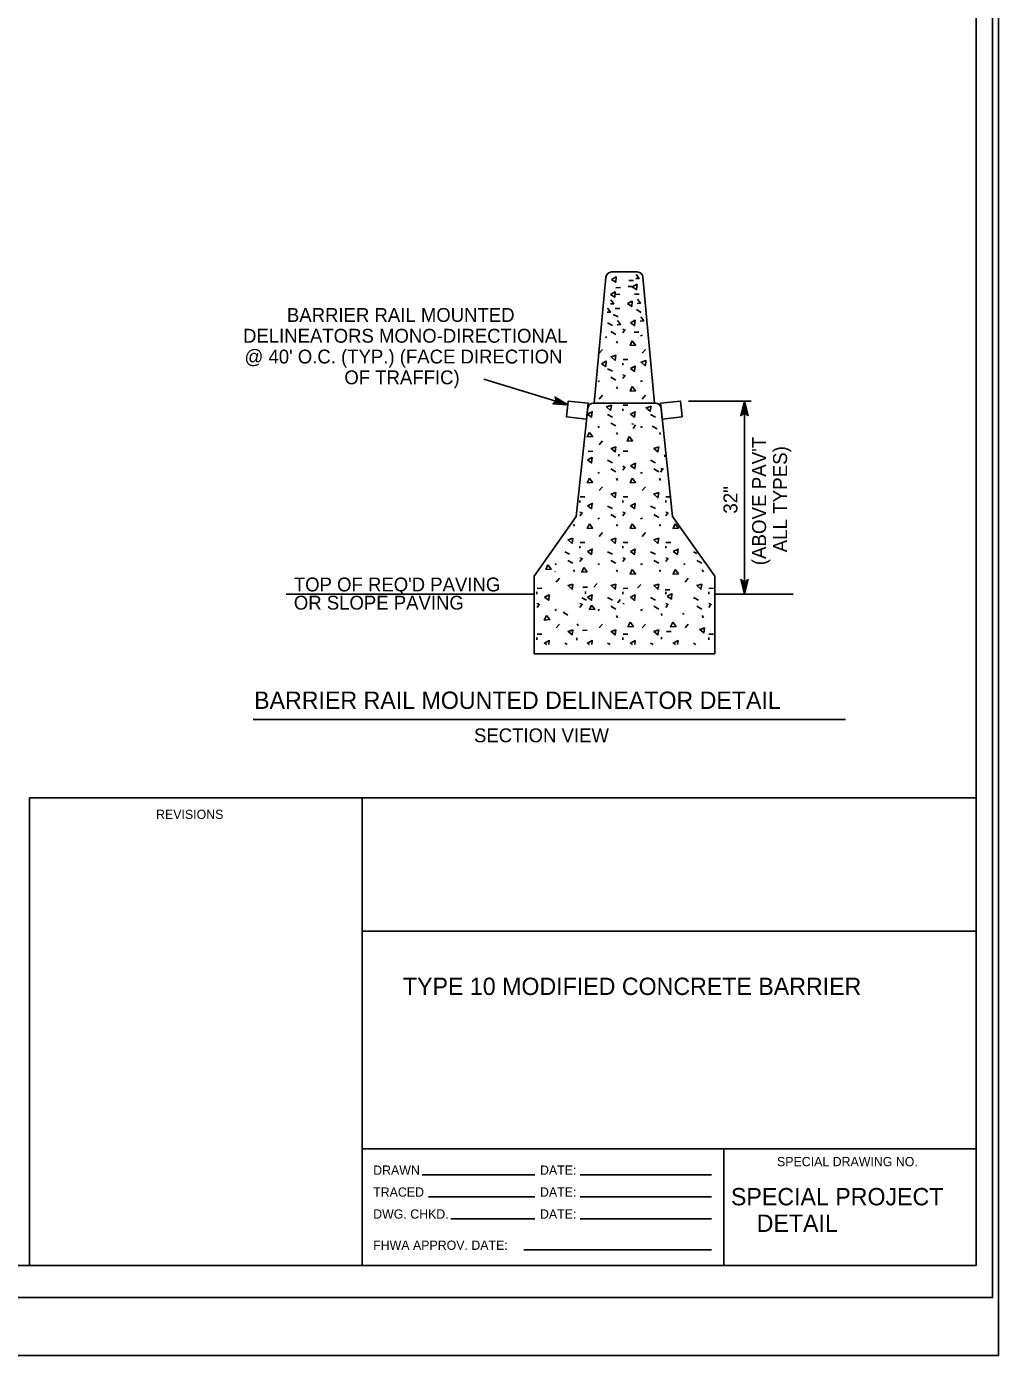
# Model space of a CAD drawing. Extents: x 504255 to 505955, y 659986 to 661086.
# Drawn here: x 505553 to 505955, y 659986 to 660536 of the extents above; entities that cross this region are included whole.
import ezdxf

# ---------------------------------------------------------------- set-up
doc = ezdxf.new("R2010")
doc.units = 0
for name, color, linetype in [('Level 62', 7, 'Continuous'), ('Level1', 7, 'Continuous'), ('Level3', 7, 'Continuous'), ('Level63', 7, 'Continuous')]:
    doc.layers.add(name, color=color, linetype=linetype)

msp = doc.modelspace()

# ---------------------------------------------------------------- linework, layer by layer
at = {"layer": 'Level 62'}
msp.add_lwpolyline([(505955.48, 661086.39), (504255.48, 661086.39), (504255.48, 659986.39), (505955.48, 659986.39)], close=True, dxfattribs=at)
at = {"layer": 'Level1'}
for p, q in [((505792.97, 660432.68), (505788.18, 660380.52)), ((505808.33, 660432.68), (505813.12, 660380.52)), ((505742.45, 660390.42), (505777.23, 660379.88)), ((505853.11, 660381.38), (505827.17, 660381.38)), ((505850.32, 660301.52), (505850.32, 660381.38)), ((505823.29, 660328.72), (505823.29, 660328.72)), ((505838.06, 660307.81), (505838.06, 660307.81)), ((505647.02, 660249.61), (505892.16, 660249.61)), ((505946.29, 660217.21), (505554.37, 660217.21)), ((505554.37, 660217.21), (505554.37, 660023.67)), ((505692.05, 660217.21), (505692.05, 660023.67)), ((505692.05, 660161.99), (505946.29, 660161.99)), ((505692.05, 660071.92), (505946.29, 660071.92)), ((505841.81, 660071.92), (505841.81, 660023.67)), ((505716.88, 660061.14), (505763.62, 660061.14)), ((505782.31, 660061.14), (505836.74, 660061.14)), ((505719.48, 660052.06), (505763.62, 660052.06)), ((505782.31, 660052.06), (505836.74, 660052.06)), ((505728.82, 660042.97), (505763.62, 660042.97)), ((505782.31, 660042.97), (505836.74, 660042.97)), ((505758.94, 660030.06), (505836.74, 660030.06)), ((505946.29, 660023.67), (505554.37, 660023.67))]:
    msp.add_line(p, q, dxfattribs=at)
for points in [[(504257.9, 660010.3), (505953.07, 660010.3), (505953.07, 661062.47), (504257.9, 661062.47), (504257.9, 660010.3)], [(504327.92, 660023.67), (505946.29, 660023.67), (505946.29, 661038.56), (504327.92, 661038.56), (504327.92, 660023.67)], [(505795.35, 660434.83), (505805.95, 660434.83)], [(505771.02, 660380.2), (505777.23, 660379.88), (505771.91, 660383.05), (505772.44, 660382.37), (505773.43, 660382.07), (505772.32, 660381.89), (505775.22, 660381.01), (505772.5, 660381.31), (505774.92, 660380.06), (505772.03, 660380.93), (505772.85, 660380.16), (505771.86, 660380.47), (505771.02, 660380.2), (505772.43, 660381.34), (505771.91, 660383.05)], [(505787.84, 660380.52), (505813.46, 660380.52)], [(505848.81, 660375.4), (505850.32, 660381.38), (505851.83, 660375.4), (505851.33, 660376.11), (505851.33, 660377.14), (505850.82, 660376.15), (505850.82, 660379.13), (505850.32, 660376.48), (505849.82, 660379.13), (505849.82, 660376.15), (505849.31, 660377.14), (505849.31, 660376.11), (505848.81, 660375.4), (505850.32, 660376.4), (505851.83, 660375.4)], [(505785.46, 660378.4), (505780.7, 660333.61)], [(505815.84, 660378.4), (505820.6, 660333.61)], [(505780.7, 660333.61), (505763.25, 660308.92)], [(505820.6, 660333.61), (505838.06, 660308.92)], [(505763.25, 660308.92), (505763.25, 660276.83)], [(505838.06, 660308.92), (505838.06, 660276.83)], [(505848.81, 660307.5), (505850.32, 660301.52), (505851.83, 660307.5), (505851.33, 660306.79), (505851.33, 660305.76), (505850.82, 660306.76), (505850.82, 660303.77), (505850.32, 660306.43), (505849.82, 660303.77), (505849.82, 660306.76), (505849.31, 660305.76), (505849.31, 660306.79), (505848.81, 660307.5), (505850.32, 660306.5), (505851.83, 660307.5)], [(505838.06, 660276.83), (505763.25, 660276.83)]]:
    msp.add_lwpolyline(points, dxfattribs=at)
for points in [[(505776.7, 660374.82), (505784.99, 660373.96), (505785.68, 660380.52), (505777.39, 660381.38)], [(505824.61, 660374.82), (505816.32, 660373.96), (505815.62, 660380.52), (505823.91, 660381.38)], [(505771.89, 660310.84), (505771.89, 660310.83), (505771.9, 660310.84)]]:
    msp.add_lwpolyline(points, close=True, dxfattribs=at)
for centre, start_param, end_param in [((505795.35, 660432.46), 4.712389, 6.192092), ((505805.95, 660432.46), 3.232686, 4.712389), ((505787.84, 660378.15), 4.712389, 6.178514), ((505813.46, 660378.15), 3.24706, 4.712389)]:
    msp.add_ellipse(centre, major_axis=(-2.39, 0), ratio=0.99, start_param=start_param, end_param=end_param, dxfattribs=at)
at = {"layer": 'Level3'}
for p, q in [((505804.37, 660431.35), (505802.41, 660431.32)), ((505798.81, 660425.58), (505796.85, 660425.55)), ((505799.08, 660428.33), (505797.12, 660428.3)), ((505804.1, 660428.78), (505802.14, 660428.74)), ((505806.79, 660425.67), (505804.83, 660425.64)), ((505798.81, 660419.73), (505796.85, 660419.69)), ((505805.62, 660419.24), (505807.58, 660418.09)), ((505793.7, 660413.71), (505795.7, 660412.65)), ((505796.04, 660417.26), (505798.03, 660416.21)), ((505792.64, 660407.68), (505793.34, 660408.01)), ((505795.02, 660410.17), (505797.08, 660408.96)), ((505800.57, 660411.03), (505799.98, 660411.21)), ((505801.02, 660411.03), (505800.02, 660409.64)), ((505806.61, 660409.87), (505804.65, 660409.84)), ((505807.36, 660408.39), (505808.07, 660408.72)), ((505791.55, 660402.75), (505790.17, 660401.15)), ((505797.35, 660406.23), (505797.77, 660405.37)), ((505809.32, 660402.75), (505807.95, 660401.15)), ((505799.98, 660397.11), (505799.98, 660396.22)), ((505802.04, 660398.6), (505800.08, 660398.56)), ((505793.7, 660394.77), (505795.7, 660393.71)), ((505795.02, 660391.23), (505797.08, 660390.02)), ((505800.57, 660392.1), (505799.98, 660392.26)), ((505801.02, 660392.1), (505800.02, 660390.7)), ((505789.59, 660389.45), (505790.3, 660389.78)), ((505797.35, 660387.29), (505797.77, 660386.43)), ((505807.36, 660389.45), (505808.07, 660389.78)), ((505791.55, 660383.81), (505790.17, 660382.21)), ((505802.04, 660379.66), (505800.08, 660379.63)), ((505809.32, 660383.81), (505807.95, 660382.21)), ((505793.7, 660375.83), (505795.7, 660374.77)), ((505799.98, 660378.17), (505799.98, 660377.28)), ((505811.49, 660375.83), (505813.47, 660374.77)), ((505789.59, 660370.51), (505790.3, 660370.83)), ((505795.02, 660372.29), (505797.08, 660371.09)), ((505804.35, 660371.81), (505803.76, 660371.99)), ((505805.3, 660371.49), (505804.3, 660370.1)), ((505807.36, 660370.51), (505808.07, 660370.83)), ((505812.1, 660371.03), (505814.16, 660369.83)), ((505791.55, 660364.87), (505790.17, 660363.27)), ((505797.35, 660368.35), (505797.77, 660367.49)), ((505815.12, 660368.35), (505815.54, 660367.49)), ((505787.64, 660360.6), (505785.67, 660360.56)), ((505798.36, 660359.46), (505798.36, 660358.58)), ((505802.04, 660360.72), (505800.08, 660360.68)), ((505817.31, 660359.19), (505817.31, 660358.3)), ((505793.7, 660356.89), (505795.7, 660355.83)), ((505795.02, 660353.34), (505797.08, 660352.14)), ((505800.57, 660354.22), (505799.98, 660354.39)), ((505801.02, 660354.22), (505800.02, 660352.83)), ((505811.49, 660356.89), (505813.47, 660355.83)), ((505812.8, 660353.34), (505814.86, 660352.14)), ((505816.64, 660353.42), (505815.65, 660352.03)), ((505816.38, 660353.33), (505815.79, 660353.5)), ((505789.59, 660351.57), (505790.3, 660351.89)), ((505797.35, 660349.41), (505797.77, 660348.55)), ((505807.36, 660351.57), (505808.07, 660351.89)), ((505815.12, 660349.41), (505815.54, 660348.55)), ((505784.27, 660341.78), (505782.31, 660341.74)), ((505791.55, 660345.93), (505790.17, 660344.33)), ((505802.04, 660341.78), (505800.08, 660341.74)), ((505809.32, 660345.93), (505807.95, 660344.33)), ((505819.82, 660341.78), (505817.86, 660341.74)), ((505782.21, 660340.29), (505782.21, 660339.4)), ((505793.7, 660337.95), (505795.7, 660336.89)), ((505799.98, 660340.29), (505799.98, 660339.4)), ((505811.49, 660337.95), (505813.47, 660336.89)), ((505817.76, 660340.29), (505817.76, 660339.4)), ((505779.57, 660330.47), (505779.99, 660329.61)), ((505782.8, 660335.27), (505782.21, 660335.45)), ((505783.24, 660335.27), (505782.25, 660333.88)), ((505789.59, 660332.63), (505790.3, 660332.95)), ((505795.02, 660334.4), (505797.08, 660333.2)), ((505797.35, 660330.47), (505797.77, 660329.61)), ((505800.57, 660335.27), (505799.98, 660335.45)), ((505801.02, 660335.27), (505800.02, 660333.88)), ((505807.36, 660332.63), (505808.07, 660332.95)), ((505812.8, 660334.4), (505814.86, 660333.2)), ((505815.12, 660330.47), (505815.54, 660329.61)), ((505818.35, 660335.27), (505817.76, 660335.45)), ((505818.79, 660335.27), (505817.8, 660333.88)), ((505791.55, 660326.99), (505790.17, 660325.39)), ((505809.32, 660326.99), (505807.95, 660325.39)), ((505775.93, 660319.01), (505777.92, 660317.96)), ((505782.21, 660321.35), (505782.21, 660320.47)), ((505784.27, 660322.84), (505782.31, 660322.8)), ((505793.7, 660319.01), (505795.7, 660317.96)), ((505799.98, 660321.35), (505799.98, 660320.47)), ((505802.04, 660322.84), (505800.08, 660322.8)), ((505811.49, 660319.01), (505813.47, 660317.96)), ((505817.76, 660321.35), (505817.76, 660320.47)), ((505819.82, 660322.84), (505817.86, 660322.8)), ((505829.26, 660319.01), (505830.68, 660318.25)), ((505771.81, 660313.7), (505772.51, 660314.01)), ((505777.25, 660315.46), (505779.31, 660314.26)), ((505782.8, 660316.34), (505782.21, 660316.51)), ((505783.24, 660316.34), (505782.25, 660314.94)), ((505789.59, 660313.7), (505790.3, 660314.01)), ((505795.02, 660315.46), (505797.08, 660314.26)), ((505800.57, 660316.34), (505799.98, 660316.51)), ((505801.02, 660316.34), (505800.02, 660314.94)), ((505807.36, 660313.7), (505808.07, 660314.01)), ((505812.8, 660315.46), (505814.86, 660314.26)), ((505818.35, 660316.34), (505817.76, 660316.51)), ((505818.79, 660316.34), (505817.8, 660314.94)), ((505825.14, 660313.7), (505825.84, 660314.01)), ((505830.58, 660315.46), (505832.63, 660314.26)), ((505773.77, 660308.05), (505772.4, 660306.45)), ((505779.57, 660311.53), (505779.99, 660310.67)), ((505797.35, 660311.53), (505797.77, 660310.67)), ((505815.12, 660311.53), (505815.54, 660310.67)), ((505827.09, 660308.05), (505825.73, 660306.45)), ((505832.9, 660311.53), (505833.32, 660310.67)), ((505766.49, 660303.9), (505764.53, 660303.86)), ((505785.33, 660304.34), (505783.37, 660304.3)), ((505784.58, 660302.54), (505784.58, 660301.65)), ((505789.32, 660305.94), (505787.95, 660304.34)), ((505802.04, 660303.9), (505800.08, 660303.86)), ((505807.46, 660305.5), (505806.08, 660303.9)), ((505819.46, 660303.26), (505817.49, 660303.22)), ((505837.59, 660303.9), (505835.63, 660303.86)), ((505764.43, 660302.41), (505764.43, 660301.52)), ((505765.02, 660297.4), (505764.43, 660297.57)), ((505765.47, 660297.4), (505764.48, 660296)), ((505782.8, 660297.4), (505782.21, 660297.57)), ((505783.24, 660297.4), (505782.25, 660296)), ((505783, 660300.01), (505784.99, 660298.95)), ((505793.7, 660300.07), (505795.7, 660299.02)), ((505798.85, 660299.32), (505797.86, 660297.93)), ((505799.98, 660302.41), (505799.98, 660301.52)), ((505800.57, 660297.4), (505799.98, 660297.57)), ((505811.49, 660300.07), (505813.47, 660299.02)), ((505817.76, 660302.41), (505817.76, 660301.52)), ((505818.35, 660297.4), (505817.76, 660297.57)), ((505818.79, 660297.4), (505817.8, 660296)), ((505829.26, 660300.07), (505831.25, 660299.02)), ((505835.53, 660302.41), (505835.53, 660301.52)), ((505836.13, 660297.4), (505835.53, 660297.57)), ((505836.57, 660297.4), (505835.58, 660296)), ((505771.81, 660294.75), (505772.51, 660295.08)), ((505775.23, 660294.02), (505777.29, 660292.81)), ((505789.59, 660294.75), (505790.3, 660295.08)), ((505795.02, 660296.53), (505797.08, 660295.32)), ((505797.35, 660292.59), (505797.77, 660291.73)), ((505807.36, 660294.75), (505808.07, 660295.08)), ((505812.8, 660296.53), (505814.86, 660295.32)), ((505815.81, 660293.5), (505816.23, 660292.63)), ((505824.68, 660293.16), (505825.39, 660293.49)), ((505830.58, 660296.53), (505832.63, 660295.32)), ((505832.9, 660292.59), (505833.32, 660291.73)), ((505773.77, 660289.11), (505772.4, 660287.52)), ((505781.06, 660289.2), (505781.48, 660288.33)), ((505785.27, 660286.52), (505783.31, 660286.47)), ((505791.55, 660289.11), (505790.17, 660287.52)), ((505809.32, 660289.11), (505807.95, 660287.52)), ((505820.03, 660286.06), (505818.07, 660286.02)), ((505827.09, 660289.11), (505825.73, 660287.52)), ((505764.43, 660283.47), (505764.43, 660282.58)), ((505766.49, 660284.96), (505764.53, 660284.92)), ((505775.93, 660281.13), (505776.92, 660280.61)), ((505780.96, 660283.34), (505780.96, 660282.45)), ((505793.7, 660281.13), (505794.7, 660280.61)), ((505799.98, 660283.47), (505799.98, 660282.58)), ((505802.04, 660284.96), (505800.08, 660284.92)), ((505811.49, 660281.13), (505812.48, 660280.61)), ((505815.96, 660283.67), (505815.96, 660282.79)), ((505829.26, 660281.13), (505830.25, 660280.61)), ((505835.53, 660283.47), (505835.53, 660282.58)), ((505837.59, 660284.96), (505835.63, 660284.92))]:
    msp.add_line(p, q, dxfattribs=at)
for points in [[(505795.32, 660431.74), (505797.06, 660430.55), (505797.27, 660432.75)], [(505803.92, 660428.73), (505805.66, 660427.53), (505805.88, 660429.74)], [(505794.87, 660425.53), (505796.62, 660424.34), (505796.83, 660426.54)], [(505801.95, 660421.72), (505803.69, 660420.52), (505803.91, 660422.72)], [(505803.11, 660413.81), (505804.86, 660412.62), (505805.08, 660414.82)], [(505803.92, 660406.32), (505803.03, 660404.4), (505805.26, 660404.56)], [(505791.17, 660396.83), (505792.91, 660395.64), (505793.12, 660397.84)], [(505797.11, 660400.37), (505795.11, 660399.7), (505796.76, 660398.21)], [(505809.6, 660398.15), (505807.58, 660397.48), (505809.24, 660395.99)], [(505803.11, 660394.88), (505804.86, 660393.68), (505805.08, 660395.88)], [(505803.92, 660387.38), (505803.03, 660385.46), (505805.26, 660385.63)], [(505795.25, 660379.7), (505793.25, 660379.02), (505794.91, 660377.53)], [(505785.34, 660375.94), (505787.08, 660374.74), (505787.3, 660376.94)], [(505803.11, 660375.94), (505804.86, 660374.74), (505805.08, 660376.94)], [(505811.66, 660379.3), (505809.65, 660378.62), (505811.31, 660377.14)], [(505786.15, 660368.43), (505785.25, 660366.52), (505787.48, 660366.7)], [(505802.68, 660366.69), (505801.79, 660364.78), (505804.02, 660364.95)], [(505785.34, 660357), (505787.08, 660355.81), (505787.3, 660358)], [(505797.11, 660362.49), (505795.11, 660361.82), (505796.76, 660360.33)], [(505814.89, 660362.49), (505812.88, 660361.82), (505814.54, 660360.33)], [(505803.22, 660354.63), (505804.96, 660353.44), (505805.18, 660355.64)], [(505786.15, 660349.5), (505785.25, 660347.58), (505787.48, 660347.75)], [(505803.92, 660349.5), (505803.03, 660347.58), (505805.26, 660347.75)], [(505797.11, 660343.56), (505795.11, 660342.88), (505796.76, 660341.4)], [(505814.89, 660343.56), (505812.88, 660342.88), (505814.54, 660341.4)], [(505785.34, 660338.05), (505787.08, 660336.86), (505787.3, 660339.06)], [(505803.11, 660338.05), (505804.86, 660336.86), (505805.08, 660339.06)], [(505786.15, 660330.55), (505785.25, 660328.65), (505787.48, 660328.81)], [(505803.92, 660330.55), (505803.03, 660328.65), (505805.26, 660328.81)], [(505821.7, 660330.55), (505820.8, 660328.65), (505823.03, 660328.81)], [(505779.34, 660324.61), (505777.33, 660323.94), (505778.99, 660322.46)], [(505797.11, 660324.61), (505795.11, 660323.94), (505796.76, 660322.46)], [(505814.89, 660324.61), (505812.88, 660323.94), (505814.54, 660322.46)], [(505785.34, 660319.12), (505787.08, 660317.92), (505787.3, 660320.12)], [(505803.11, 660319.12), (505804.86, 660317.92), (505805.08, 660320.12)], [(505820.89, 660319.12), (505822.64, 660317.92), (505822.85, 660320.12)], [(505769.01, 660313.6), (505768.12, 660311.7), (505770.35, 660311.86)], [(505783.89, 660312.5), (505783, 660310.6), (505785.22, 660310.76)], [(505803.92, 660311.61), (505803.03, 660309.71), (505805.26, 660309.87)], [(505821.7, 660311.61), (505820.8, 660309.71), (505823.03, 660309.87)], [(505779.34, 660305.67), (505777.33, 660305), (505778.99, 660303.51)], [(505797.11, 660305.67), (505795.11, 660305), (505796.76, 660303.51)], [(505814.89, 660305.67), (505812.88, 660305), (505814.54, 660303.51)], [(505832.66, 660305.67), (505830.65, 660305), (505832.31, 660303.51)], [(505767.56, 660300.17), (505769.31, 660298.98), (505769.52, 660301.18)], [(505785.34, 660300.17), (505787.08, 660298.98), (505787.3, 660301.18)], [(505803.11, 660300.17), (505804.86, 660298.98), (505805.08, 660301.18)], [(505818.34, 660300.63), (505820.08, 660299.44), (505820.3, 660301.64)], [(505768.37, 660292.68), (505767.48, 660290.77), (505769.71, 660290.93)], [(505787.06, 660296.98), (505786.17, 660295.07), (505788.39, 660295.23)], [(505779.34, 660286.73), (505777.33, 660286.06), (505778.99, 660284.57)], [(505797.11, 660286.73), (505795.11, 660286.06), (505796.76, 660284.57)], [(505803.01, 660289.84), (505802.11, 660287.94), (505804.35, 660288.1)], [(505814.89, 660286.73), (505812.88, 660286.06), (505814.54, 660284.57)], [(505820.67, 660289.84), (505819.78, 660287.94), (505822.01, 660288.1)], [(505833.84, 660287.56), (505831.83, 660286.89), (505833.49, 660285.4)]]:
    msp.add_lwpolyline(points, close=True, dxfattribs=at)
for points in [[(505805.32, 660432.07), (505806.75, 660432.18), (505805.51, 660433.8)], [(505805.86, 660421.78), (505807.28, 660421.88), (505806.04, 660423.5)], [(505793.5, 660418.14), (505794.92, 660418.24), (505793.68, 660419.86)], [(505794.84, 660421.6), (505796.26, 660421.7), (505795.02, 660423.33)], [(505797.62, 660412.99), (505799.04, 660413.09), (505797.8, 660414.72)], [(505807.21, 660414.5), (505808.63, 660414.6), (505807.39, 660416.22)], [(505769.36, 660280.61), (505769.52, 660282.24), (505767.56, 660281.24), (505768.48, 660280.61)], [(505787.14, 660280.61), (505787.3, 660282.24), (505785.34, 660281.24), (505786.26, 660280.61)], [(505804.91, 660280.61), (505805.08, 660282.24), (505803.11, 660281.24), (505804.04, 660280.61)], [(505822.69, 660280.61), (505822.85, 660282.24), (505820.89, 660281.24), (505821.81, 660280.61)]]:
    msp.add_lwpolyline(points, dxfattribs=at)
at = {"layer": 'Level63'}
for p, q in [((505763.25, 660301.52), (505660.67, 660301.52)), ((505838.06, 660301.52), (505870.56, 660301.52)), ((505787.16, 660280.61), (505787.16, 660280.61)), ((505838.06, 660280.61), (505838.06, 660280.61))]:
    msp.add_line(p, q, dxfattribs=at)

# ---------------------------------------------------------------- texts
at = {"layer": 'Level1'}
for s, height, p in [('BARRIER RAIL MOUNTED', 5.7394, (505660.93, 660414.16)), ('DELINEATORS MONO-DIRECTIONAL', 5.7394, (505642.76, 660405.55)), ("@ 40' O.C. (TYP.) (FACE DIRECTION", 5.7394, (505643.37, 660396.94)), ('OF TRAFFIC)', 5.7394, (505684.7, 660388.33)), ("TOP OF REQ'D PAVING ", 5.7392, (505663.79, 660302.61)), ('OR SLOPE PAVING', 5.7392, (505663.79, 660295.08)), ('BARRIER RAIL MOUNTED DELINEATOR DETAIL', 7.1744, (505647.35, 660253.98)), ('SECTION VIEW', 5.7395, (505738.38, 660240.17)), ('REVISIONS', 3.826, (505606.77, 660208.42)), ('TYPE 10 MODIFIED CONCRETE BARRIER', 7.1739, (505708.96, 660135.57)), ('SPECIAL DRAWING NO.', 3.8261, (505863.83, 660064.7)), ('DRAWN', 3.826, (505696.63, 660061.17)), ('DATE:', 3.826, (505765.7, 660061.17)), ('TRACED', 3.826, (505696.63, 660052.09)), ('DATE:', 3.826, (505765.7, 660052.09)), ('SPECIAL PROJECT', 7.1739, (505844.75, 660048.51)), ('DWG. CHKD.', 3.826, (505696.63, 660043)), ('DATE:', 3.826, (505765.7, 660043)), ('    DETAIL', 7.174, (505844.75, 660037.51)), ('FHWA APPROV. DATE:', 3.8261, (505696.63, 660030.09))]:
    msp.add_text(s, height=height, dxfattribs=at).set_placement(p)
for s, height, p in [("(ABOVE PAV'T", 5.7971, (505859.29, 660313.42)), ('ALL TYPES)', 5.797, (505867.99, 660318.79)), ('32"', 5.797, (505847.44, 660334.79))]:
    msp.add_text(s, height=height, rotation=90, dxfattribs=at).set_placement(p)

doc.saveas('drawing.dxf')
